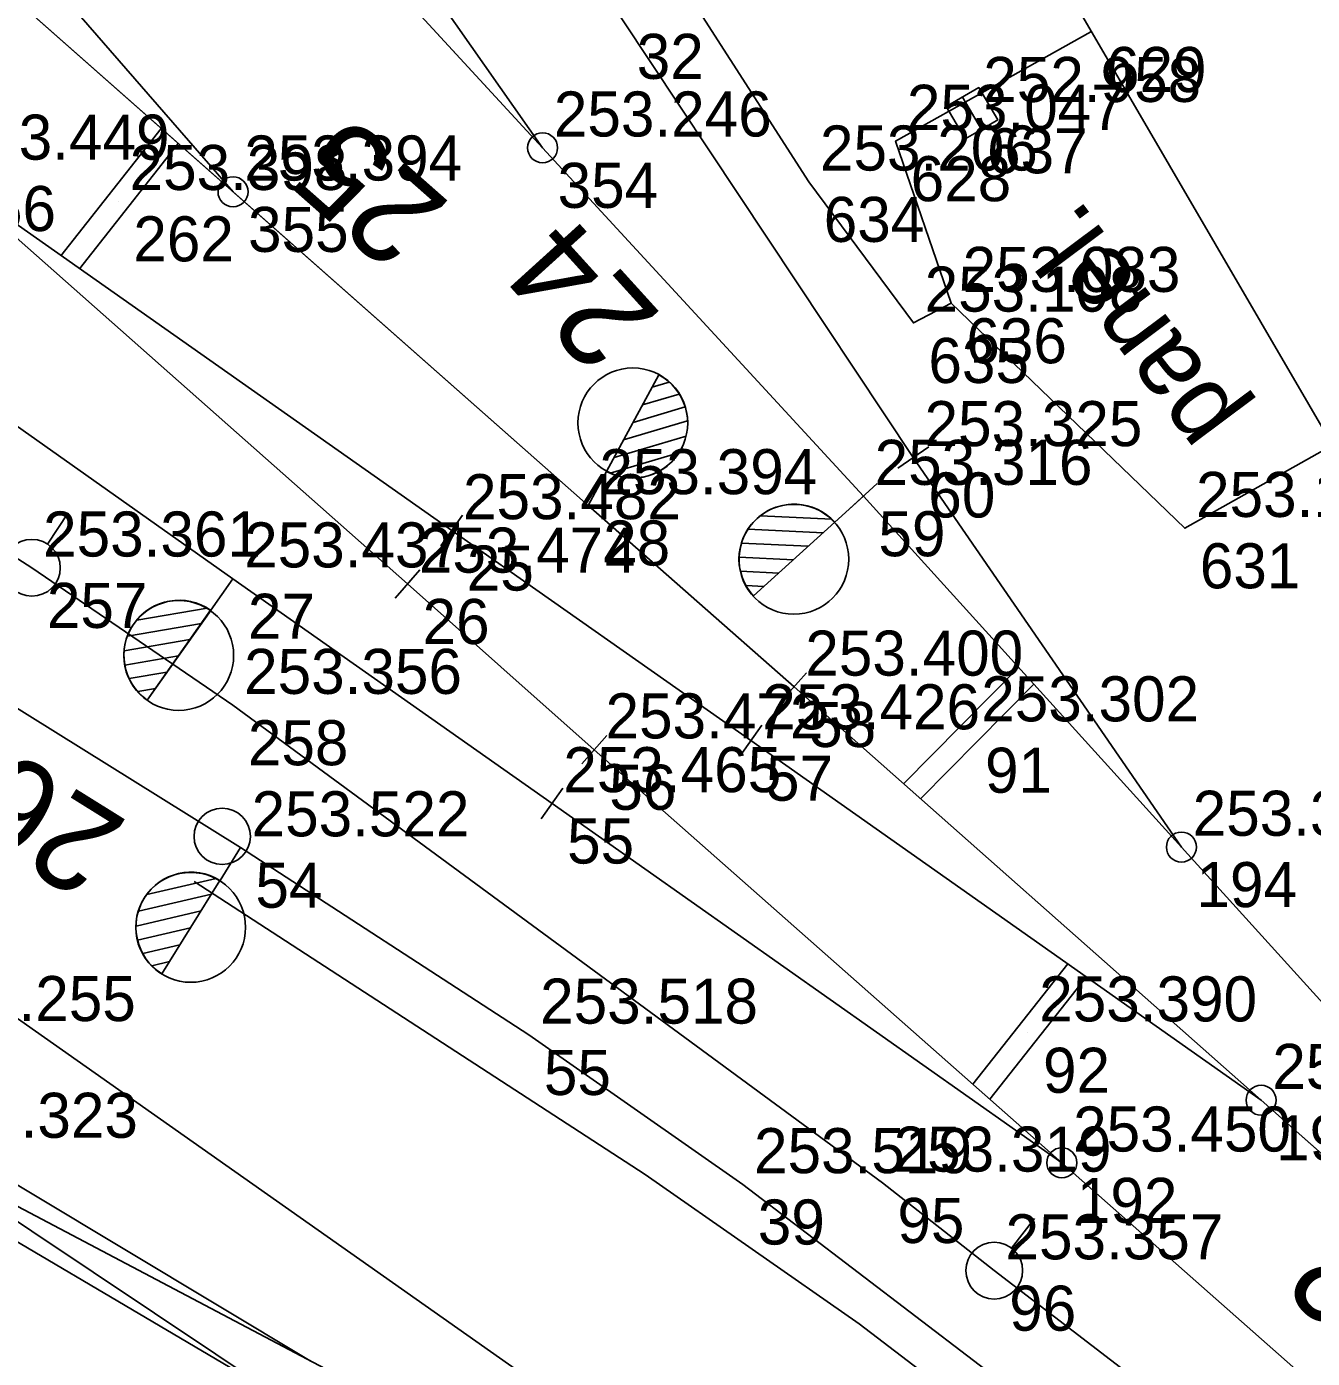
# Model space of a CAD drawing. Extents: x -496688 to -495455, y -1089309 to -1088026.
# Drawn here: x -496017.77 to -495983.54, y -1088607.59 to -1088572.14 of the extents above; entities that cross this region are included whole.
import ezdxf

# ---------------------------------------------------------------- set-up
doc = ezdxf.new("R2010")
doc.units = 0
for name, color, linetype in [('Vrstva 1', 7, 'Continuous'), ('Vrstva 16', 7, 'Continuous'), ('Vrstva 2', 7, 'Continuous'), ('Vrstva 23', 7, 'Continuous'), ('Vrstva 36', 7, 'Continuous'), ('Vrstva 43', 7, 'Continuous'), ('Vrstva 49', 7, 'Continuous'), ('Vrstva 60', 7, 'Continuous'), ('Vrstva 61', 7, 'Continuous'), ('Vrstva 7', 7, 'Continuous')]:
    doc.layers.add(name, color=color, linetype=linetype)

msp = doc.modelspace()

# ---------------------------------------------------------------- linework, layer by layer
at = {"layer": 'Vrstva 1'}
for points in [[(-495794.281, -1088769.662), (-495806.718, -1088758.644), (-495819.114, -1088747.662), (-495828.107, -1088739.648), (-495840.608, -1088728.579), (-495852.984, -1088717.621), (-495860.029, -1088711.42), (-495872.461, -1088700.397), (-495884.955, -1088689.319), (-495893.533, -1088681.721), (-495913.179, -1088664.263), (-495947.105, -1088634.191), (-495952.116, -1088629.76), (-495964.613, -1088618.686), (-495984.901, -1088600.717), (-495997.336, -1088589.715), (-496002.819, -1088584.884), (-496021.751, -1088568.167), (-496024.418, -1088565.811), (-496062.504, -1088532.205), (-496086.773, -1088510.767), (-496106.199, -1088493.629), (-496127.249, -1088474.987), (-496164.633, -1088441.927)], [(-495916.136, -1088667.962), (-495923.285, -1088661.656), (-495935.688, -1088650.668), (-495948.162, -1088639.613), (-495977.755, -1088613.379), (-495990.206, -1088602.384), (-496002.656, -1088591.386), (-496007.627, -1088586.973), (-496020.065, -1088575.979), (-496027.948, -1088569.009), (-496033.091, -1088564.46), (-496045.526, -1088553.442), (-496057.996, -1088542.394), (-496059.439, -1088541.128), (-496090.012, -1088514.139), (-496109.155, -1088497.226), (-496130.335, -1088478.506), (-496167.718, -1088445.393)], [(-496004.032, -1088575.362), (-496011.275, -1088565.036), (-496022.068, -1088550.141), (-496029.461, -1088539.924), (-496036.884, -1088529.665), (-496046.952, -1088515.759), (-496054.33, -1088505.532), (-496061.713, -1088495.299), (-496072.458, -1088480.37)], [(-495994.162, -1088583.605), (-496001.925, -1088571.928), (-496007.411, -1088562.975), (-496027.558, -1088528.593)], [(-496012.274, -1088576.534), (-496020.611, -1088566.947), (-496028.03, -1088558.476), (-496036.319, -1088548.972), (-496044.622, -1088539.452)], [(-495990.206, -1088602.384), (-496003.779, -1088592.817), (-496012.278, -1088586.834), (-496025.85, -1088577.242), (-496039.444, -1088567.637), (-496047.813, -1088561.646)], [(-495875.462, -1088716.542), (-495884.273, -1088707.491), (-495892.725, -1088698.131), (-495899.76, -1088690.34), (-495906.824, -1088682.54), (-495918.092, -1088670.104), (-495924.53, -1088662.996), (-495935.688, -1088650.668), (-495946.859, -1088638.317), (-495948.839, -1088636.121), (-495953.409, -1088631.059), (-495964.613, -1088618.686), (-495975.723, -1088606.415), (-495978.55, -1088603.323), (-495987.022, -1088593.978), (-495995.49, -1088584.636), (-496004.032, -1088575.362), (-496012.801, -1088565.84)], [(-496006.199, -1088611.844), (-496020.907, -1088602.019), (-496035.815, -1088592.055), (-496044.874, -1088586.073), (-496053.125, -1088580.797), (-496061.169, -1088575.721), (-496076.529, -1088566.028)], [(-495903.705, -1088678.98), (-495917.323, -1088669.371), (-495925.246, -1088663.805), (-495938.946, -1088654.176), (-495952.525, -1088644.634), (-495954.862, -1088642.985), (-495958.022, -1088640.767), (-495972.56, -1088630.52), (-495979.681, -1088625.505), (-495986.807, -1088620.489), (-496002.959, -1088609.142), (-496027.436, -1088591.913), (-496060.399, -1088568.783)], [(-496012.079, -1088593.993), (-496026.182, -1088585.205), (-496040.299, -1088576.406), (-496041.612, -1088575.586)], [(-495984.901, -1088600.717), (-495998.484, -1088591.144), (-496006.45, -1088585.55), (-496020.065, -1088575.979)], [(-495986.807, -1088620.489), (-496002.996, -1088611.501), (-496004.514, -1088610.662), (-496020.907, -1088602.019), (-496037.47, -1088593.294), (-496040.369, -1088591.776), (-496048.068, -1088587.699), (-496063.641, -1088579.453)], [(-495987.022, -1088593.978), (-495994.162, -1088583.605)], [(-495980.867, -1088617.126), (-495987.952, -1088611.164), (-495998.702, -1088602.96), (-496004.397, -1088598.979), (-496012.079, -1088593.993)]]:
    msp.add_lwpolyline(points, dxfattribs=at)
at = {"layer": 'Vrstva 16'}
for points in [[(-495993.149, -1088579.499), (-495994.159, -1088580.024), (-495996.946, -1088576.268), (-496003.309, -1088566.364), (-495995.598, -1088561.834)], [(-495983.043, -1088583.306), (-495986.932, -1088585.49), (-495993.149, -1088579.499), (-495994.631, -1088575.184), (-495989.431, -1088572.278)]]:
    msp.add_lwpolyline(points, dxfattribs=at)
at = {"layer": 'Vrstva 2'}
for p, q in [((-496002.331, -1088583.978), (-496000.935, -1088581.405)), ((-496000.935, -1088581.405), (-496002.33, -1088583.978)), ((-496001.115, -1088581.739), (-496000.659, -1088581.604)), ((-496001.369, -1088582.206), (-496000.395, -1088581.917)), ((-496001.622, -1088582.673), (-496000.238, -1088582.261)), ((-496001.876, -1088583.139), (-496000.173, -1088582.633)), ((-496002.128, -1088583.604), (-496000.213, -1088583.036)), ((-496002.228, -1088584.025), (-496000.407, -1088583.485)), ((-495994.574, -1088583.888), (-495993.75, -1088583.322)), ((-496002.332, -1088583.979), (-496002.819, -1088584.884)), ((-496002.33, -1088583.978), (-496002.331, -1088583.978)), ((-495995.86, -1088584.972), (-495995.12, -1088584.3)), ((-495996.25, -1088585.329), (-495995.49, -1088584.636)), ((-496006.162, -1088585.141), (-496006.738, -1088585.959)), ((-495996.25, -1088585.329), (-495998.42, -1088587.294)), ((-495998.42, -1088587.294), (-495996.251, -1088585.329)), ((-495996.332, -1088585.251), (-495998.228, -1088585.157)), ((-495996.251, -1088585.329), (-495996.25, -1088585.329)), ((-495996.565, -1088585.615), (-495998.561, -1088585.517)), ((-495996.958, -1088585.971), (-495998.732, -1088585.884)), ((-495997.352, -1088586.327), (-495998.794, -1088586.256)), ((-496007.296, -1088586.598), (-496007.958, -1088587.348)), ((-495997.745, -1088586.682), (-495998.759, -1088586.633)), ((-496012.869, -1088587.675), (-496012.278, -1088586.834)), ((-495998.138, -1088587.039), (-495998.614, -1088587.016)), ((-496012.966, -1088587.617), (-496014.838, -1088587.938)), ((-496014.56, -1088590.066), (-496012.87, -1088587.675)), ((-496012.869, -1088587.676), (-496014.56, -1088590.066)), ((-496012.87, -1088587.675), (-496012.869, -1088587.676)), ((-496013.115, -1088588.023), (-496015.084, -1088588.362)), ((-496013.421, -1088588.456), (-496015.171, -1088588.757)), ((-496013.728, -1088588.889), (-496015.151, -1088589.133)), ((-496014.034, -1088589.322), (-496015.035, -1088589.494)), ((-495997.667, -1088590.089), (-495997.005, -1088589.341)), ((-496014.34, -1088589.755), (-496014.81, -1088589.836)), ((-496002.987, -1088591.761), (-496002.325, -1088591.011)), ((-495998.772, -1088591.553), (-495998.196, -1088590.735)), ((-496004.067, -1088593.226), (-496003.491, -1088592.408)), ((-496012.62, -1088594.867), (-496012.079, -1088593.993)), ((-496012.721, -1088594.815), (-496014.57, -1088595.244)), ((-496014.169, -1088597.352), (-496012.621, -1088594.867)), ((-496012.621, -1088594.868), (-496014.169, -1088597.352)), ((-496012.621, -1088594.867), (-496012.621, -1088594.868)), ((-496012.845, -1088595.229), (-496014.792, -1088595.681)), ((-496013.126, -1088595.678), (-496014.856, -1088596.08)), ((-496013.407, -1088596.129), (-496014.814, -1088596.455)), ((-496013.688, -1088596.578), (-496014.677, -1088596.808)), ((-496013.968, -1088597.029), (-496014.433, -1088597.137))]:
    msp.add_line(p, q, dxfattribs=at)
for points in [[(-496004.032, -1088575.362), (-496011.275, -1088565.036)], [(-495995.49, -1088584.636), (-496004.032, -1088575.362), (-496012.79, -1088565.852)], [(-496012.274, -1088576.534), (-496020.611, -1088566.947)], [(-496012.278, -1088586.834), (-496025.85, -1088577.242), (-496039.444, -1088567.637)], [(-496002.819, -1088584.884), (-496012.274, -1088576.534), (-496021.751, -1088568.167)], [(-496027.948, -1088569.009), (-496020.065, -1088575.979), (-496007.627, -1088586.973)], [(-496020.065, -1088575.979), (-496006.45, -1088585.55)], [(-496012.079, -1088593.993), (-496026.182, -1088585.205), (-496040.299, -1088576.406)], [(-495987.022, -1088593.978), (-495994.162, -1088583.605)], [(-495978.55, -1088603.323), (-495987.022, -1088593.978), (-495995.49, -1088584.636)], [(-495977.016, -1088607.689), (-495984.901, -1088600.717), (-495997.336, -1088589.715)], [(-495977.755, -1088613.379), (-495990.206, -1088602.384), (-496002.656, -1088591.386)], [(-495984.901, -1088600.717), (-495998.484, -1088591.144)], [(-496006.199, -1088611.844), (-496020.907, -1088602.019), (-496035.815, -1088592.056)], [(-495990.206, -1088602.384), (-496003.779, -1088592.817)], [(-496004.514, -1088610.662), (-496020.907, -1088602.019), (-496037.47, -1088593.294)], [(-496010.223, -1088607.652), (-496032.433, -1088594.316)], [(-496011.072, -1088608.589), (-496032.972, -1088595.663)]]:
    msp.add_lwpolyline(points, dxfattribs=at)
for centre, radius in [((-496004.032, -1088575.362), 0.4), ((-496012.274, -1088576.534), 0.4), ((-496001.628, -1088582.686), 1.462), ((-495997.342, -1088586.316), 1.462), ((-496013.72, -1088588.877), 1.462), ((-495987.022, -1088593.978), 0.4), ((-496013.401, -1088596.116), 1.462), ((-495984.901, -1088600.717), 0.4), ((-495990.206, -1088602.384), 0.4)]:
    msp.add_circle(centre, radius, dxfattribs=at)
for centre, start, end in [((-496001.633, -1088582.692), 241.5428, 61.5036), ((-495997.335, -1088586.312), 42.2103, 222.1712), ((-496013.715, -1088588.871), 54.7686, 234.7295), ((-496013.395, -1088596.11), 58.0913, 238.0521)]:
    msp.add_arc(centre, 1.464, start, end, dxfattribs=at)
at = {"layer": 'Vrstva 23'}
msp.add_lwpolyline([(-495974.045, -1088579.399), (-495982.418, -1088584.284), (-495997.256, -1088558.819), (-496003.517, -1088548.12), (-496034.293, -1088496.252), (-496025.968, -1088491.27), (-495995.168, -1088543.196), (-495974.045, -1088579.399)], dxfattribs=at)
at = {"layer": 'Vrstva 36'}
for p, q in [((-496017.213, -1088585.913), (-496016.663, -1088585.078)), ((-495991.543, -1088604.656), (-495990.931, -1088603.865))]:
    msp.add_line(p, q, dxfattribs=at)
msp.add_lwpolyline([(-495982.001, -1088613.178), (-495986.312, -1088609.628), (-495992.007, -1088605.254), (-495994.985, -1088602.919), (-496012.279, -1088590.201), (-496017.631, -1088586.544), (-496026.239, -1088581.024), (-496029.453, -1088578.634), (-496040.554, -1088570.808), (-496043.73, -1088568.341), (-496063.489, -1088552.926), (-496089.159, -1088531.511), (-496093.567, -1088527.59), (-496121.596, -1088502.694)], dxfattribs=at)
for centre in [(-496017.631, -1088586.543), (-495992.007, -1088605.253)]:
    msp.add_circle(centre, 0.757, dxfattribs=at)
at = {"layer": 'Vrstva 43'}
msp.add_lwpolyline([(-495992.346, -1088574.874), (-495992.778, -1088575.126), (-495993.282, -1088574.262), (-495992.418, -1088573.758), (-495991.914, -1088574.622), (-495992.346, -1088574.874), (-495992.85, -1088574.01)], dxfattribs=at)
at = {"layer": 'Vrstva 49'}
msp.add_lwpolyline([(-495935.845, -1088657.888), (-495950.312, -1088645.117), (-495977.766, -1088620.838), (-495984.851, -1088614.876), (-495995.601, -1088606.672), (-496001.296, -1088602.691), (-496013.309, -1088594.893)], dxfattribs=at)
at = {"layer": 'Vrstva 60'}
for p, q in [((-495989.431, -1088572.278), (-495989.431, -1088572.278)), ((-495989.431, -1088572.278), (-495989.431, -1088572.278)), ((-495992.598, -1088574.442), (-495992.598, -1088574.442)), ((-495992.598, -1088574.442), (-495992.598, -1088574.442)), ((-496004.032, -1088575.362), (-496004.032, -1088575.362)), ((-496004.032, -1088575.362), (-496004.032, -1088575.362)), ((-495994.631, -1088575.184), (-495994.631, -1088575.184)), ((-495994.631, -1088575.184), (-495994.631, -1088575.184)), ((-495996.946, -1088576.268), (-495996.946, -1088576.268)), ((-495996.946, -1088576.268), (-495996.946, -1088576.268)), ((-496015.329, -1088576.786), (-496015.329, -1088576.786)), ((-496015.329, -1088576.786), (-496015.329, -1088576.786)), ((-496012.274, -1088576.534), (-496012.274, -1088576.534)), ((-496012.274, -1088576.534), (-496012.274, -1088576.534)), ((-495993.149, -1088579.499), (-495993.149, -1088579.499)), ((-495993.149, -1088579.499), (-495993.149, -1088579.499)), ((-495994.159, -1088580.024), (-495994.159, -1088580.024)), ((-495994.159, -1088580.024), (-495994.159, -1088580.024)), ((-495994.162, -1088583.605), (-495994.162, -1088583.605)), ((-495994.162, -1088583.605), (-495994.162, -1088583.605)), ((-495995.49, -1088584.636), (-495995.49, -1088584.636)), ((-495995.49, -1088584.636), (-495995.49, -1088584.636)), ((-496002.819, -1088584.884), (-496002.819, -1088584.884)), ((-496002.819, -1088584.884), (-496002.819, -1088584.884)), ((-496006.45, -1088585.55), (-496006.45, -1088585.55)), ((-496006.45, -1088585.55), (-496006.45, -1088585.55)), ((-495986.932, -1088585.49), (-495986.932, -1088585.49)), ((-495986.932, -1088585.49), (-495986.932, -1088585.49)), ((-496017.631, -1088586.544), (-496017.631, -1088586.544)), ((-496017.631, -1088586.544), (-496017.631, -1088586.544)), ((-496012.278, -1088586.834), (-496012.278, -1088586.834)), ((-496012.278, -1088586.834), (-496012.278, -1088586.834)), ((-496007.627, -1088586.973), (-496007.627, -1088586.973)), ((-496007.627, -1088586.973), (-496007.627, -1088586.973)), ((-495997.336, -1088589.715), (-495997.336, -1088589.715)), ((-495997.336, -1088589.715), (-495997.336, -1088589.715)), ((-496012.279, -1088590.201), (-496012.279, -1088590.201)), ((-496012.279, -1088590.201), (-496012.279, -1088590.201)), ((-495992.652, -1088590.932), (-495992.652, -1088590.932)), ((-495992.652, -1088590.932), (-495992.652, -1088590.932)), ((-496002.656, -1088591.386), (-496002.656, -1088591.386)), ((-496002.656, -1088591.386), (-496002.656, -1088591.386)), ((-495998.484, -1088591.144), (-495998.484, -1088591.144)), ((-495998.484, -1088591.144), (-495998.484, -1088591.144)), ((-496003.779, -1088592.817), (-496003.779, -1088592.817)), ((-496003.779, -1088592.817), (-496003.779, -1088592.817)), ((-496012.079, -1088593.993), (-496012.079, -1088593.993)), ((-496012.079, -1088593.993), (-496012.079, -1088593.993)), ((-495987.022, -1088593.978), (-495987.022, -1088593.978)), ((-495987.022, -1088593.978), (-495987.022, -1088593.978)), ((-496004.397, -1088598.979), (-496004.397, -1088598.979)), ((-496004.397, -1088598.979), (-496004.397, -1088598.979)), ((-495991.108, -1088598.92), (-495991.108, -1088598.92)), ((-495991.108, -1088598.92), (-495991.108, -1088598.92)), ((-495984.901, -1088600.717), (-495984.901, -1088600.717)), ((-495984.901, -1088600.717), (-495984.901, -1088600.717)), ((-495990.206, -1088602.384), (-495990.206, -1088602.384)), ((-495990.206, -1088602.384), (-495990.206, -1088602.384)), ((-495998.702, -1088602.96), (-495998.702, -1088602.96)), ((-495998.702, -1088602.96), (-495998.702, -1088602.96)), ((-495994.985, -1088602.919), (-495994.985, -1088602.919)), ((-495994.985, -1088602.919), (-495994.985, -1088602.919)), ((-495992.007, -1088605.254), (-495992.007, -1088605.254)), ((-495992.007, -1088605.254), (-495992.007, -1088605.254))]:
    msp.add_line(p, q, dxfattribs=at)
at = {"layer": 'Vrstva 7'}
for p, q in [((-496016.855, -1088578.236), (-496014.183, -1088574.849)), ((-496016.364, -1088578.581), (-496013.733, -1088575.247)), ((-495994.421, -1088592.295), (-495991.358, -1088589.195)), ((-495993.97, -1088592.693), (-495990.954, -1088589.64)), ((-495992.574, -1088600.292), (-495990.045, -1088597.091)), ((-495992.124, -1088600.69), (-495989.554, -1088597.438))]:
    msp.add_line(p, q, dxfattribs=at)
msp.add_circle((-496012.561, -1088593.693), 0.75, dxfattribs=at)

# ---------------------------------------------------------------- texts
at = {"layer": 'Vrstva 16'}
msp.add_text('panel.', height=2, rotation=126.7612, dxfattribs=at).set_placement((-495985.419, -1088582.503))
at = {"layer": 'Vrstva 2'}
for s, rotation, p in [('25', 138.5863, (-496006.442, -1088576.874)), ('24', 132.1905, (-496000.828, -1088579.831)), ('26', 148.0717, (-496015.015, -1088593.326)), ('22', 138.4688, (-495979.952, -1088606.355))]:
    msp.add_text(s, height=2.5, rotation=rotation, dxfattribs=at).set_placement(p)
at = {"layer": 'Vrstva 60'}
for s, p in [('32', (-496001.525, -1088573.528)), ('32', (-496001.525, -1088573.528)), ('629', (-495989.031, -1088573.878)), ('629', (-495989.031, -1088573.878)), ('637', (-495992.198, -1088576.042)), ('637', (-495992.198, -1088576.042)), ('354', (-496003.632, -1088576.962)), ('354', (-496003.632, -1088576.962)), ('628', (-495994.231, -1088576.784)), ('628', (-495994.231, -1088576.784)), ('356', (-496019.665, -1088577.579)), ('356', (-496019.665, -1088577.579)), ('634', (-495996.546, -1088577.868)), ('634', (-495996.546, -1088577.868)), ('262', (-496014.929, -1088578.386)), ('262', (-496014.929, -1088578.386)), ('355', (-496011.874, -1088578.134)), ('355', (-496011.874, -1088578.134)), ('636', (-495992.749, -1088581.099)), ('636', (-495992.749, -1088581.099)), ('635', (-495993.759, -1088581.624)), ('635', (-495993.759, -1088581.624)), ('60', (-495993.762, -1088585.205)), ('60', (-495993.762, -1088585.205)), ('28', (-496002.419, -1088586.484)), ('28', (-496002.419, -1088586.484)), ('59', (-495995.09, -1088586.236)), ('59', (-495995.09, -1088586.236)), ('25', (-496006.05, -1088587.15)), ('25', (-496006.05, -1088587.15)), ('631', (-495986.532, -1088587.09)), ('631', (-495986.532, -1088587.09)), ('257', (-496017.231, -1088588.144)), ('257', (-496017.231, -1088588.144)), ('27', (-496011.878, -1088588.434)), ('27', (-496011.878, -1088588.434)), ('26', (-496007.227, -1088588.573)), ('26', (-496007.227, -1088588.573)), ('58', (-495996.936, -1088591.315)), ('58', (-495996.936, -1088591.315)), ('258', (-496011.879, -1088591.801)), ('258', (-496011.879, -1088591.801)), ('91', (-495992.252, -1088592.532)), ('91', (-495992.252, -1088592.532)), ('57', (-495998.084, -1088592.744)), ('57', (-495998.084, -1088592.744)), ('56', (-496002.256, -1088592.986)), ('56', (-496002.256, -1088592.986)), ('55', (-496003.379, -1088594.417)), ('55', (-496003.379, -1088594.417)), ('54', (-496011.679, -1088595.593)), ('54', (-496011.679, -1088595.593)), ('194', (-495986.622, -1088595.578)), ('194', (-495986.622, -1088595.578)), ('55', (-496003.997, -1088600.579)), ('55', (-496003.997, -1088600.579)), ('92', (-495990.708, -1088600.52)), ('92', (-495990.708, -1088600.52)), ('193', (-495984.501, -1088602.317)), ('193', (-495984.501, -1088602.317)), ('192', (-495989.806, -1088603.984)), ('192', (-495989.806, -1088603.984)), ('39', (-495998.302, -1088604.56)), ('39', (-495998.302, -1088604.56)), ('95', (-495994.585, -1088604.519)), ('95', (-495994.585, -1088604.519)), ('96', (-495991.607, -1088606.854)), ('96', (-495991.607, -1088606.854))]:
    msp.add_text(s, height=1.2, dxfattribs=at).set_placement(p)
at = {"layer": 'Vrstva 61'}
for s, p in [('252.958', (-495992.298, -1088574.142)), ('252.958', (-495992.298, -1088574.142)), ('253.047', (-495994.331, -1088574.884)), ('253.047', (-495994.331, -1088574.884)), ('253.246', (-496003.732, -1088575.062)), ('253.246', (-496003.732, -1088575.062)), ('253.449', (-496019.765, -1088575.679)), ('253.449', (-496019.765, -1088575.679)), ('253.394', (-496011.974, -1088576.234)), ('253.394', (-496011.974, -1088576.234)), ('253.206', (-495996.646, -1088575.968)), ('253.206', (-495996.646, -1088575.968)), ('253.398', (-496015.029, -1088576.486)), ('253.398', (-496015.029, -1088576.486)), ('253.083', (-495992.849, -1088579.199)), ('253.083', (-495992.849, -1088579.199)), ('253.108', (-495993.859, -1088579.724)), ('253.108', (-495993.859, -1088579.724)), ('253.325', (-495993.862, -1088583.305)), ('253.325', (-495993.862, -1088583.305)), ('253.316', (-495995.19, -1088584.336)), ('253.316', (-495995.19, -1088584.336)), ('253.394', (-496002.519, -1088584.584)), ('253.394', (-496002.519, -1088584.584)), ('253.482', (-496006.15, -1088585.25)), ('253.482', (-496006.15, -1088585.25)), ('253.139', (-495986.632, -1088585.19)), ('253.139', (-495986.632, -1088585.19)), ('253.361', (-496017.331, -1088586.244)), ('253.361', (-496017.331, -1088586.244)), ('253.437', (-496011.978, -1088586.534)), ('253.437', (-496011.978, -1088586.534)), ('253.474', (-496007.327, -1088586.673)), ('253.474', (-496007.327, -1088586.673)), ('253.400', (-495997.036, -1088589.415)), ('253.400', (-495997.036, -1088589.415)), ('253.356', (-496011.979, -1088589.901)), ('253.356', (-496011.979, -1088589.901)), ('253.302', (-495992.352, -1088590.632)), ('253.302', (-495992.352, -1088590.632)), ('253.472', (-496002.356, -1088591.086)), ('253.472', (-496002.356, -1088591.086)), ('253.426', (-495998.184, -1088590.844)), ('253.426', (-495998.184, -1088590.844)), ('253.465', (-496003.479, -1088592.517)), ('253.465', (-496003.479, -1088592.517)), ('253.350', (-495986.722, -1088593.678)), ('253.350', (-495986.722, -1088593.678)), ('253.522', (-496011.779, -1088593.693)), ('253.522', (-496011.779, -1088593.693)), ('253.255', (-496020.663, -1088598.611)), ('253.255', (-496020.663, -1088598.611)), ('253.390', (-495990.808, -1088598.62)), ('253.390', (-495990.808, -1088598.62)), ('253.518', (-496004.097, -1088598.679)), ('253.518', (-496004.097, -1088598.679)), ('253.377', (-495984.601, -1088600.417)), ('253.377', (-495984.601, -1088600.417)), ('253.323', (-496020.607, -1088601.719)), ('253.323', (-496020.607, -1088601.719)), ('253.450', (-495989.906, -1088602.084)), ('253.450', (-495989.906, -1088602.084)), ('253.519', (-495998.402, -1088602.66)), ('253.519', (-495998.402, -1088602.66)), ('253.319', (-495994.685, -1088602.619)), ('253.319', (-495994.685, -1088602.619)), ('253.357', (-495991.707, -1088604.954)), ('253.357', (-495991.707, -1088604.954))]:
    msp.add_text(s, height=1.2, dxfattribs=at).set_placement(p)

doc.saveas('drawing.dxf')
